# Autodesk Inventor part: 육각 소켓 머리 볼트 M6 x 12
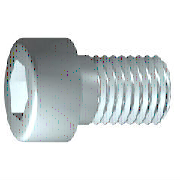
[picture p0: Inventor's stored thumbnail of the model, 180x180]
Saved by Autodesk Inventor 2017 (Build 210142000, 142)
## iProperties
IsCustomPart: 1
Created: 2012-02
Part Number: 육각 소켓 머리 볼트 M6 x 12
Material: 강철, 연강
Description: 원통형 머리 캡 나사
Document SubType Name: Modeling
Standard: JIS B 1176
Designer: mdu-01
Standards Organization: JIS
Language: ko-KR
Size Designation: M6 x 12
Categories: <MemberInstance><Categories><Category DisplayName="조임쇠" InternalName="e4da775c-781d-43d5-af7c-5136215cf5a6" Mnemonic="FSTN"><Category DisplayName="볼트" InternalN
Density: 1 g/cm^3
Appearance: 강철
Author: mdu-01
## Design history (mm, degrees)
sketch "스케치1"
  geometry: L1 (-1.333, 0)-(12, 0); L2 (12, 0)-(12, 3); L3 (12, 3)-(2.5, 3); L4 (2.5, 3)-(1.886, 3); L5 (1.886, 3)-(0, 3); L6 (0, 3)-(0, 5); L7 (0, 5)-(-6, 5); L8 (-6, 5)-(-6, 2.887); L9 (-6, 2.887)-(-3, 2.887); L10 (-3, 2.887)-(-1.333, 0); L11 (-9.6, 0)-(15.6, 0) reference; L12 (0, -1)-(0, 6) reference; L13 (2.5, 3)-(0, 3)
  constraints: 22 end point, 6 parallel, 2 collinear, 2 perpendicular, 1 horizontal, 1 point on line
  dimensions: "d1" = 9.5 distance from line of L3.end L2 (= GEL); "d2" = 0.61355 distance of L4.end L3.end (computed from GAL); "d3" = 6 distance between parallel lines of L8 L6 (= KOH); "d4" = 3 distance of L8.end L9.end (= INTI); "d5" = 60 deg angle of L10 L1; "d6" = 6 diameter of L3 L1 (= GD); "d7" = 6 diameter of L5 L1 (= BDM); "d8" = 5.7735 diameter of L9 L1 (= 1.1547 x SW); "d9" = 10 diameter of L7 L1 (= KOD); "d26" = 12 distance between parallel lines of L12 L2 (= NLG)
revolve "본체" sketch "스케치1" stored, may be unused: angle "d10" = 90 deg
sketch "스케치2"
  geometry: L1 (0, -7)-(0, 7) reference; L2 (-7, 0)-(7, 0) reference; L3 (2.887, 0)-(1.443, -2.5); L4 (1.443, -2.5)-(-1.443, -2.5); L5 (-1.443, -2.5)-(-2.887, 0); L6 (-2.887, 0)-(-1.443, 2.5); L7 (-1.443, 2.5)-(1.443, 2.5); L8 (1.443, 2.5)-(2.887, 0); 2 further points
  constraints: 12 end point, 1 coincident, 1 horizontal alignment, 1 point on line, 12 other
extrude "슬롯" join sketch "스케치2" stored distance "d11" = 10; taper "d12" = 0 deg
workplane "Work Plane1"
fillet "Fillet2" dims "d30" = 0.1 (= R)
body "Solid1"
fillet "모깎기1" dims "d17" = 0.6 (= RR)
feature "스레드" dims "d13" = 9.5 (= GEL), "d14" = 0
chamfer "모따기1" distance "d15" = 0.61345 (= -0.5 x SPD + 0.5 x GD); stored, may be unused: second distance "d16" = 0.61345 (= GUL), angle "d27" = 45 deg
other parameters: "GD" = 6 (= NND) [user parameter; used in 2 equation terms], "NLG" = 12 [user parameter; used in 1 equation term], "GEL" = 9.5 [user parameter; used in 2 equation terms], "KOD" = 10 [user parameter; used in 1 equation term], "KOH" = 6 [user parameter; used in 1 equation term], "INTI" = 3 [user parameter; used in 1 equation term], "GAL" = 0.61345 (= 0.61345 x PTC) [user parameter; used in 1 equation term], "GUL" = 0.61345 (= 0.61345 x PTC) [user parameter; used in 1 equation term], "BDM" = 6 (= NND) [user parameter; used in 1 equation term], "SW" = 5 [user parameter; used in 2 equation terms], "RR" = 0.6 [user parameter; used in 1 equation term], "SPD" = 4.7731 (= NND - 1.2269 x PTC) [user parameter; used in 1 equation term], "d19" = 0, "d28" = 0, "d29" = 0, "R" = 0.1 [user parameter; used in 1 equation term], "PHH" = 0.25 [user parameter], "GD1" = 4.7731 (= THREADDIA - 1.2269 x PTC) [user parameter], "THREADDIA" = 6 [user parameter; used in 1 equation term], "FAWI" = 45 deg [user parameter], "PTC" = 1 [user parameter; used in 5 equation terms], "NND" = 6 [user parameter; used in 3 equation terms], "TOA" = 30 deg [user parameter], "E0" = 5.775 (= 1.155 x SW) [user parameter]
